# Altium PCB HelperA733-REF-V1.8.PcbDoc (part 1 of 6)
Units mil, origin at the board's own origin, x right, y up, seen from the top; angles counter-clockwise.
Board outline 5905.51 x 4133.86 mil, 2 copper layers (Top, Bottom), stack 12.7 mil thick; 475 components, 355 nets, 1867 pads, 1471 vias.
Unrouted connection lines stored in the file: 1178.
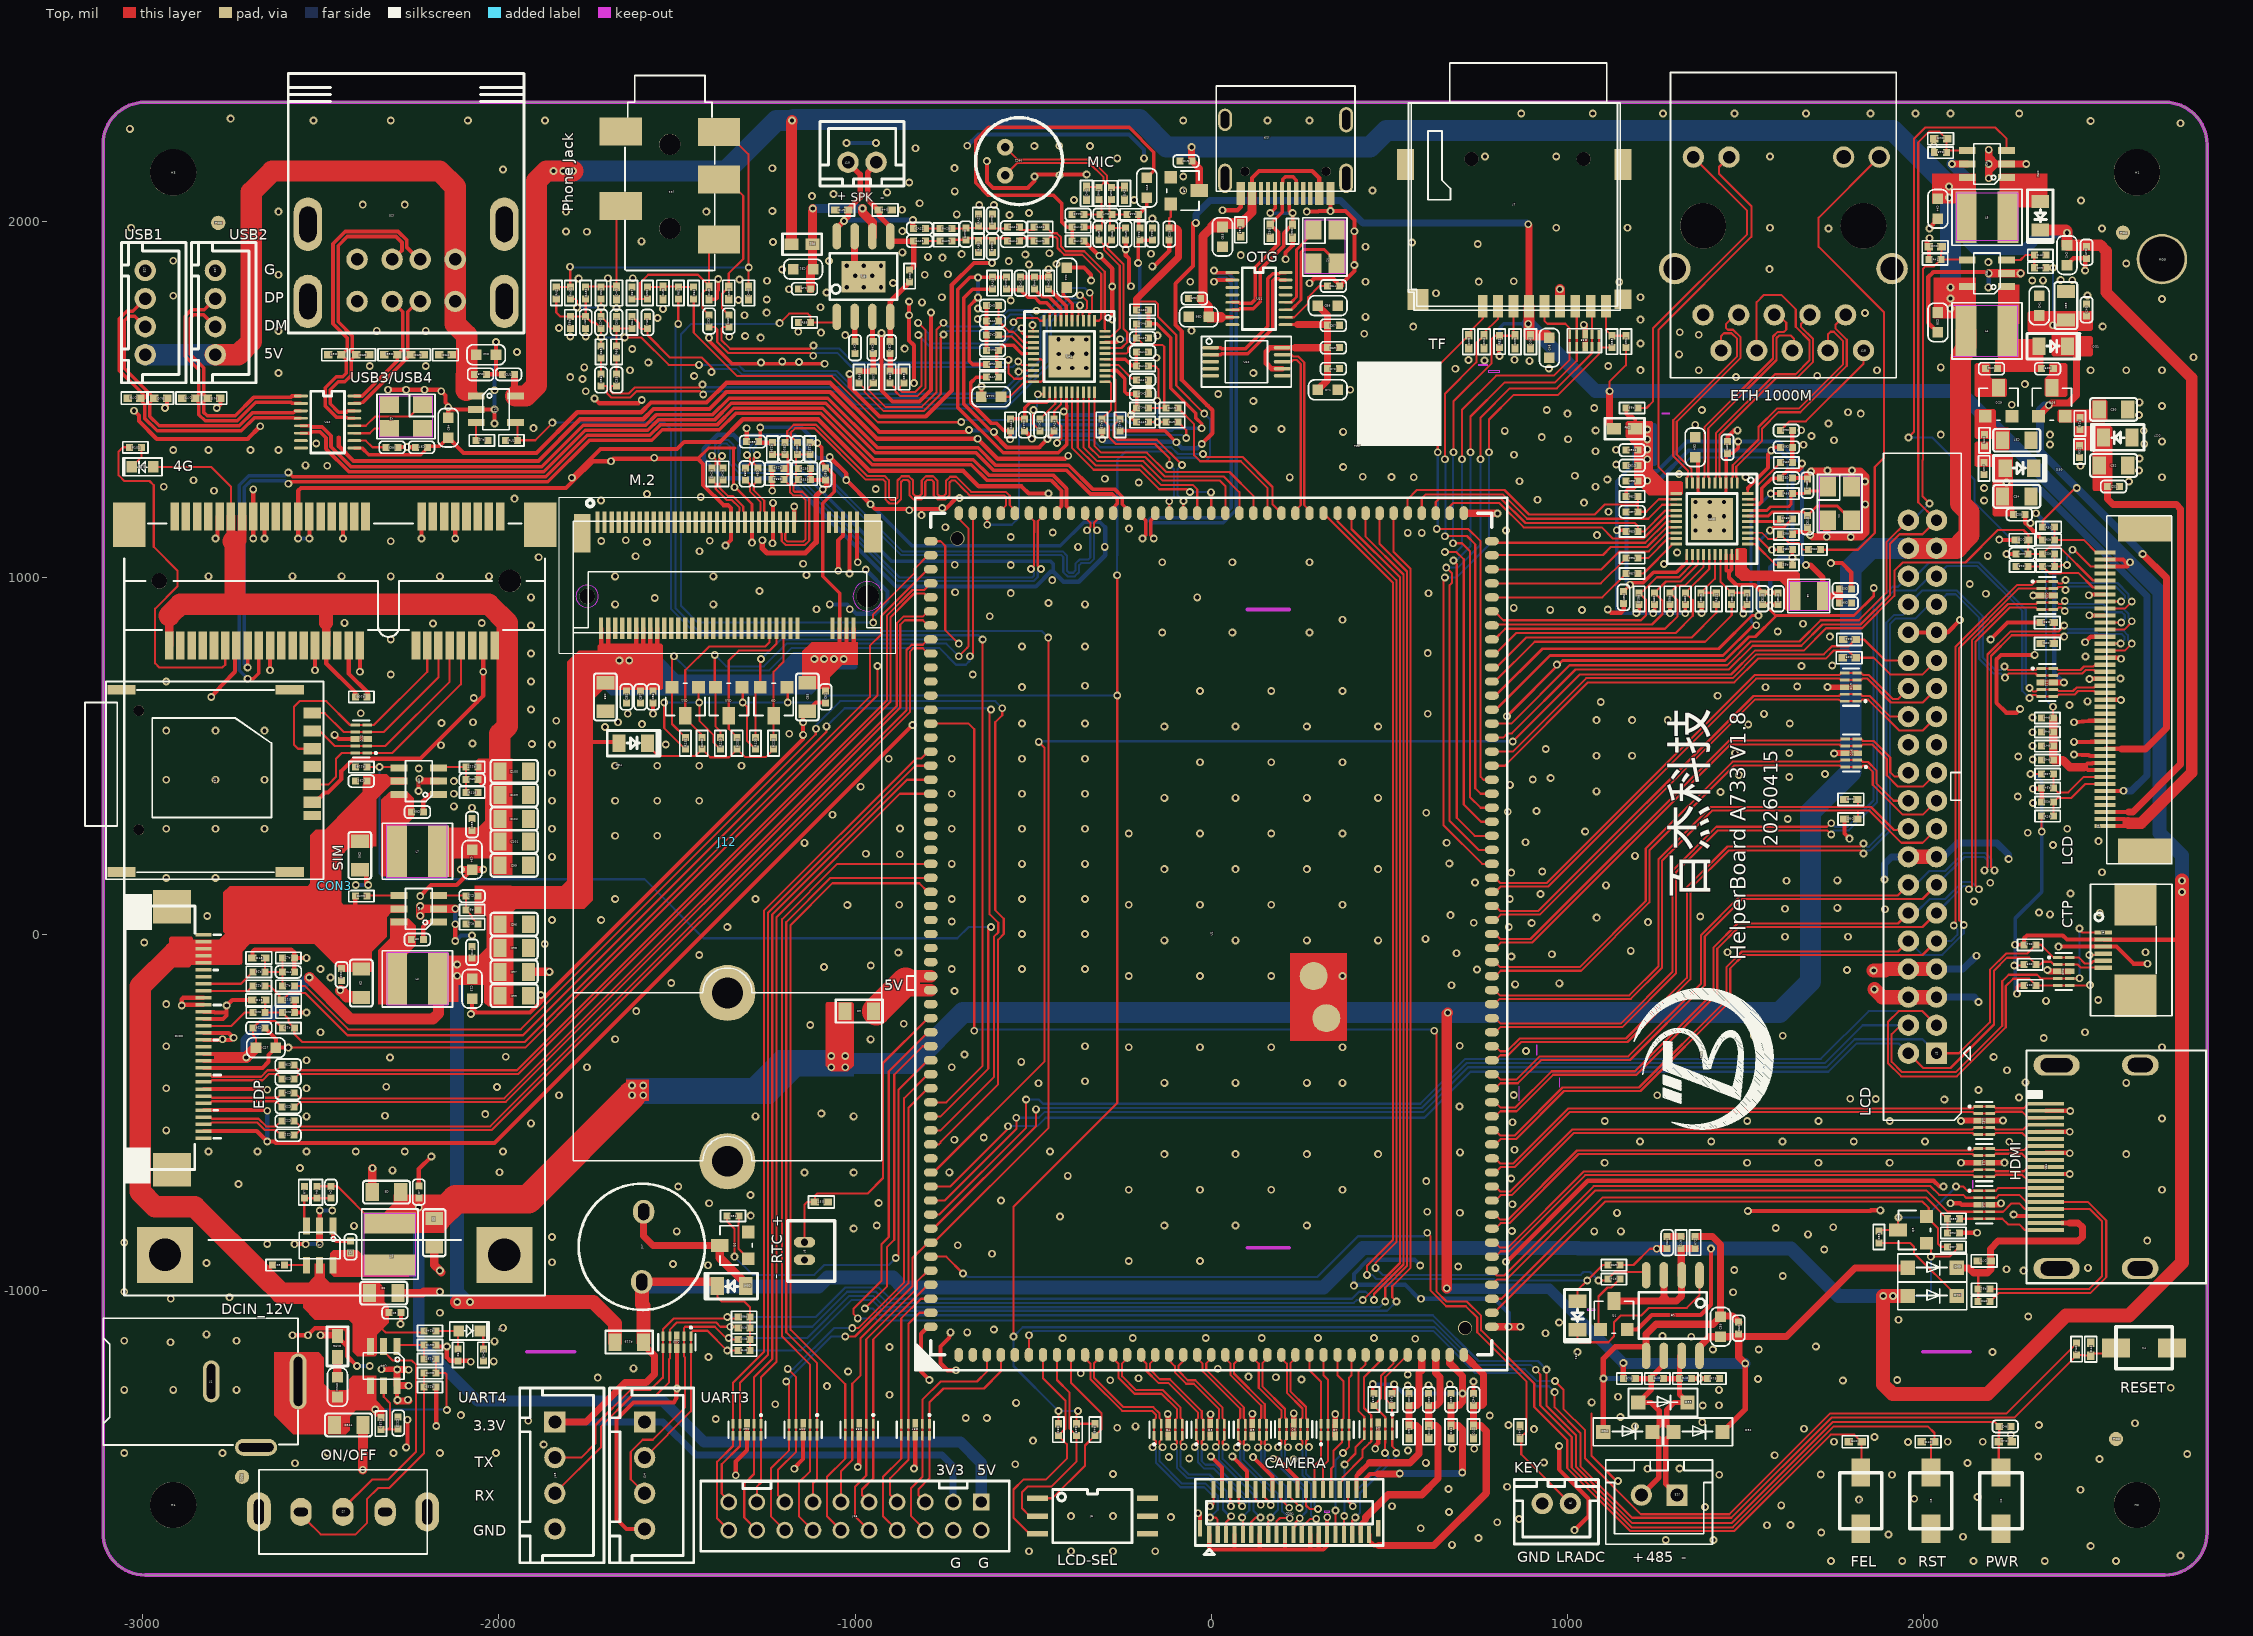
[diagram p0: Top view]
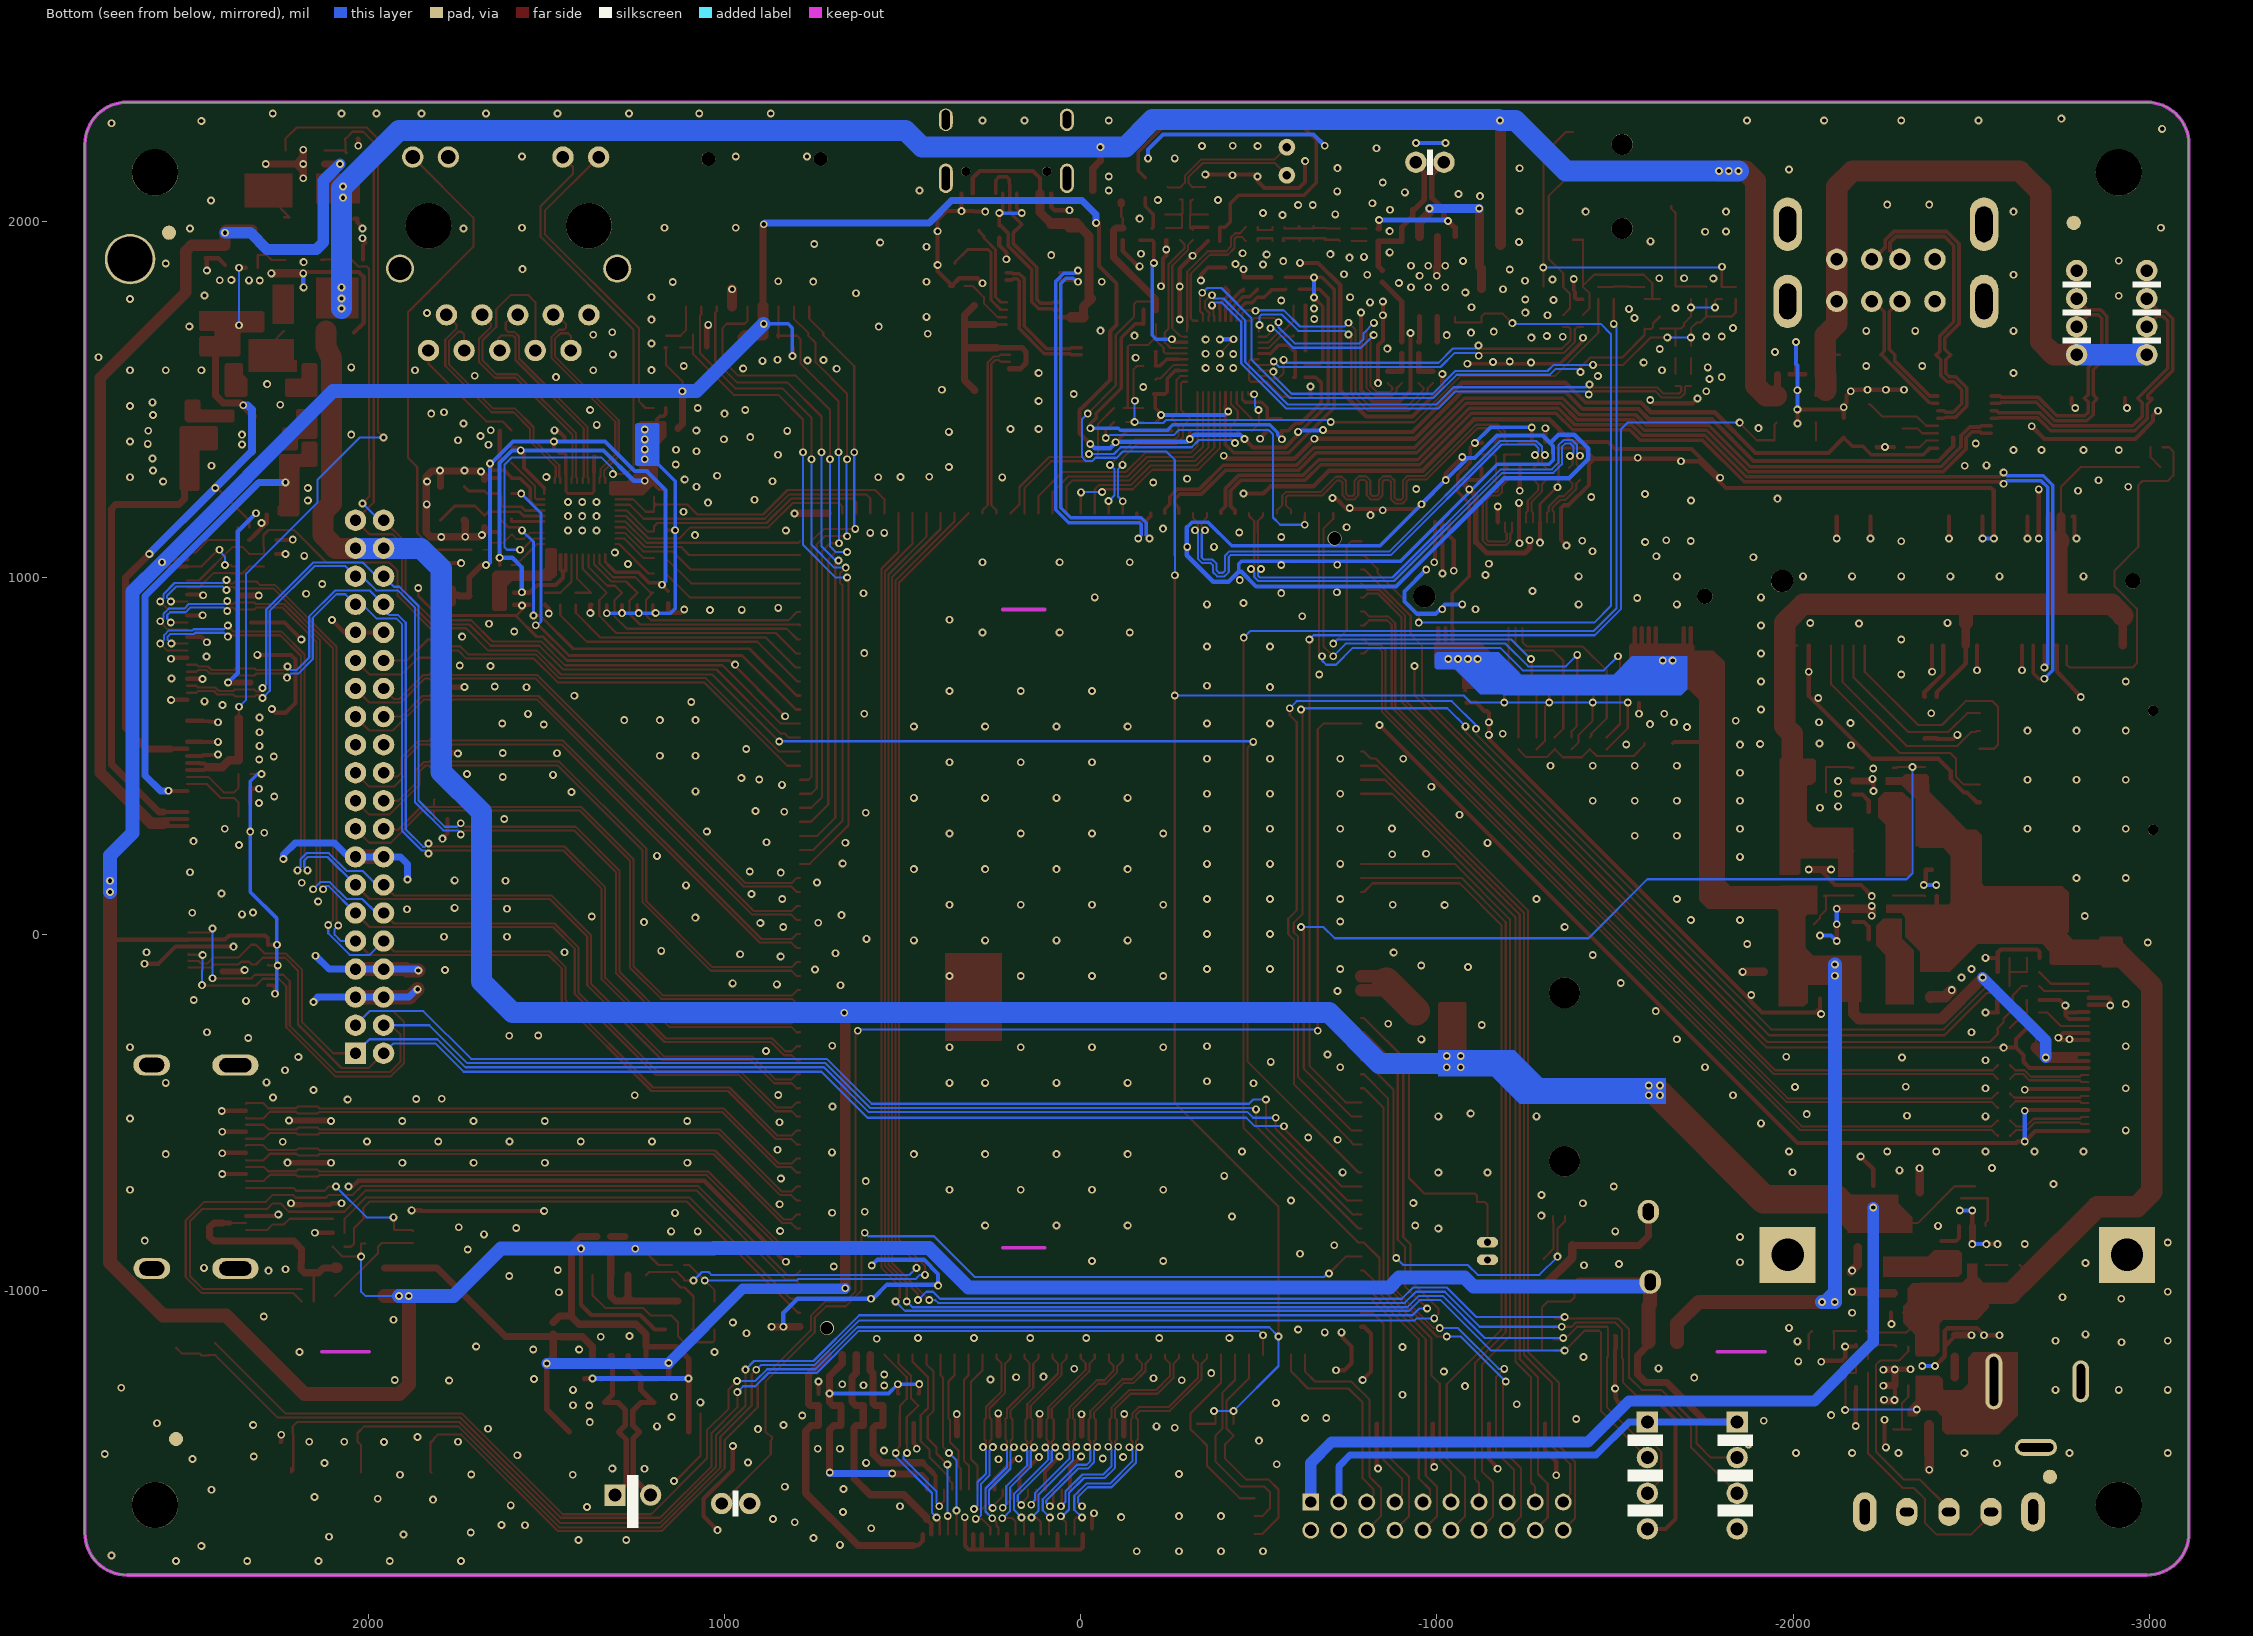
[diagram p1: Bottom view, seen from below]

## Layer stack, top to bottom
Solder Mask Top: solder mask 0.4, Solder Resist, Dk 3.5
Top: signal copper 1.35
Dielectric 1: dielectric 10, FR-4, Dk 4.3
Bottom: signal copper 1.35
Solder Mask Bottom: solder mask 0.4, Solder Resist, Dk 3.5

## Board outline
-3110.65,2216.54 cw(c-2992.54,2216.54) -2992.54,2334.65 2676.76,2334.65 cw(c2676.76,2216.54) 2794.87,2216.54 2794.87,-1681.1 cw(c2676.76,-1681.1) 2676.76,-1799.21 -2992.54,-1799.21 cw(c-2992.54,-1681.1) -3110.65,-1681.1

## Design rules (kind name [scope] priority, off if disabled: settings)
Clearance "Clearance - Net - DCIN" [InNet('DCIN')] p1: gap=6 ignorepadtopadclearanceinfootprint=FALSE except(0: Arc-Hole Track-Hole SMDPad-Hole THPad-Hole Via-Hole Fill-Hole Poly-Hole Region-Hole Text-Hole; 4: Arc-Arc Arc-Track Track-Track; 7.87: Arc-Fill Arc-Poly Arc-Region Track-Fill Track-Poly Track-Region SMDPad-Fill SMDPad-Poly SMDPad-Region THPad-Fill THPad-Poly THPad-Region Via-Fill Via-Poly Via-Region; 10: Fill-Fill Fill-Poly Fill-Region Poly-Poly Poly-Region Region-Region Text-Text)
Clearance "Clearance - Net - 340_3V3" [InNet('340_3V3') OR InNet('LED1_AD1')] p2: gap=6 ignorepadtopadclearanceinfootprint=FALSE except(0: Arc-Hole Track-Hole SMDPad-Hole THPad-Hole Via-Hole Fill-Hole Poly-Hole Region-Hole Text-Hole; 10: Fill-Fill Fill-Poly Fill-Region Poly-Poly Poly-Region Region-Region Text-Text; 12: Arc-Fill Arc-Poly Arc-Region Track-Fill Track-Poly Track-Region SMDPad-Fill SMDPad-Poly SMDPad-Region THPad-Fill THPad-Poly THPad-Region Via-Fill Via-Poly Via-Region)
Clearance "Clearance - Net - GND" [InNet('GND')] p3: gap=6 ignorepadtopadclearanceinfootprint=FALSE except(0: Arc-Hole Track-Hole SMDPad-Hole THPad-Hole Via-Hole Fill-Hole Poly-Hole Region-Hole Text-Hole; 8: Arc-Fill Arc-Poly Arc-Region Track-Fill Track-Poly Track-Region SMDPad-Fill SMDPad-Poly SMDPad-Region THPad-Fill THPad-Poly THPad-Region Via-Fill Via-Poly Via-Region; 10: Fill-Fill Fill-Poly Fill-Region Poly-Poly Poly-Region Region-Region Text-Text)
Clearance "Clearance - Net - 12V-IN" [InNet('12V-IN')] p4: gap=11.81 ignorepadtopadclearanceinfootprint=FALSE except(0: Arc-Hole Track-Hole SMDPad-Hole THPad-Hole Via-Hole Fill-Hole Poly-Hole Region-Hole Text-Hole; 10: Fill-Fill Fill-Poly Fill-Region Poly-Poly Poly-Region Region-Region Text-Text)
Clearance "Clearance - Default - DEFAULT- SMD" [IsVia vs IsSMTPin] p5: gap=0 ignorepadtopadclearanceinfootprint=FALSE
Clearance "Clearance - Default - DEFAULT - Via" [IsVia vs IsVia] p6: gap=0 ignorepadtopadclearanceinfootprint=FALSE
Clearance "Clearance - Default - DEFAULT - Net" [All] p7: gap=6 ignorepadtopadclearanceinfootprint=FALSE except(0: Arc-Hole Track-Hole SMDPad-Hole THPad-Hole Via-Hole Fill-Hole Poly-Hole Region-Hole Text-Hole; 4: Arc-Arc Arc-Track Track-Track; 10: Fill-Fill Fill-Poly Fill-Region Poly-Poly Poly-Region Region-Region Text-Text)
ComponentClearance "ComponentClearance - Default - DEFAULT" [All] p1: gap=6 collisioncheckmode=3 verticalgap=10 showdistances=FALSE
FanoutControl Fanout_SOIC [IsSOIC] p1: bgadir=Out bgaviamode=Centered fanoutstyle=Auto fanoutdirection=Alternating viagrid=1 // Fanout_SOIC (Default Rule)
FanoutControl Fanout_Small [(CompPinCount < 5)] p2: bgadir=Out bgaviamode=Centered fanoutstyle=Auto fanoutdirection=OutThenIn viagrid=1 // Fanout_Small (Default Rule)
FanoutControl Fanout_LCC [IsLCC] p3: bgadir=Out bgaviamode=Centered fanoutstyle=Auto fanoutdirection=Alternating viagrid=1 // Fanout_LCC (Default Rule)
FanoutControl Fanout_BGA [IsBGA] p4: bgadir=Out bgaviamode=Centered fanoutstyle=Auto fanoutdirection=Alternating viagrid=1 // Fanout_BGA (Default Rule)
HoleToHoleClearance "HoleToHoleClearance - Default - DEFAULT" [All] p1: gap=6 allowstackedmicrovias=TRUE
Length "Length - NetClass - HighSpeedClass_10(RuleSet)" [InNetClass('HighSpeedClass_10(RuleSet)')] p1: maxlimit=50000 minlimit=0
Length "Length - NetClass - MLNetGroup4" [InNetClass('MLNetGroup4')] p2: maxlimit=18503.27 minlimit=0
Length "Default Length" [All] p3: maxlimit=50000 minlimit=0
MatchedLengths "MatchedLengths - NetClass - HighSpeedClass_10(RuleSet)" [InNetClass('HighSpeedClass_10(RuleSet)')] p1: tolerance=200 checknetsindiffpair=FALSE checkdiffpairvsdiffpair=TRUE checkxsignals=TRUE checkothers=TRUE
MatchedLengths "MatchedLengths - NetClass - MLNetGroup4" [InNetClass('MLNetGroup4')] p2: tolerance=200 checknetsindiffpair=FALSE checkdiffpairvsdiffpair=TRUE checkxsignals=TRUE checkothers=TRUE
MaxMinImpedance "Default Impedance" [All] p1: minimum=50.00 maximum=150.0
ParallelSegment "ParallelSegment - NetClass - HighSpeedClass_10(RuleSet)_1" [InNetClass('HighSpeedClass_10(RuleSet)') vs InNetClass('HighSpeedClass_10(RuleSet)')] p1: limit=1000 gap=200
ParallelSegment "ParallelSegment - NetClass - HighSpeedClass_10(RuleSet)" [InNetClass('HighSpeedClass_10(RuleSet)') vs InNetClass('HighSpeedClass_10(RuleSet)')] p2: limit=1000 gap=200
ParallelSegment "Default Parallel Segment Adjasent" [All] p3: limit=1000 gap=200
ParallelSegment "Default Parallel Segment Same Layer" [All] p4: limit=1000 gap=200
PlaneConnect "Default PlaneConnect" [All] p1: planeconnectstyle=Relief reliefexpansion=20 reliefentries=0 reliefconductorwidth=15 reliefairgap=10
PolygonConnect "PolygonConnect - Default SMT" [IsSMTPin] p1: connectstyle=Relief reliefconductorwidth=10 reliefentries=4 polygonreliefangle="90 Angle" airgapwidth=10
PolygonConnect "PolygonConnect - Default Pad" [All] p2: connectstyle=Relief reliefconductorwidth=15 reliefentries=4 polygonreliefangle="45 Angle" airgapwidth=10
RoutingLayers "RoutingLayers - Default - DEFAULT" [All] p1: top layer_v5=TRUE bottom layer_v5=TRUE
RoutingPriority "RoutingPriority - Default - DEFAULT" [All] p1: routingpriority=3
RoutingTopology "Default Routing Topology" [All] p1: topology=Shortest
RoutingVias "RoutingVias - Default - DEFAULT" [All] p1: holewidth=12 width=22 viastyle="Through Hole" minholewidth=12 minwidth=22 maxholewidth=12 maxwidth=22
SMDToCorner "SMDToCorner - Default - DEFAULT" [All] p1: distance=0
SolderMaskExpansion [All] p1: expansion=4
Width "Width - Net - LED1_AD1" [InNet('LED1_AD1')] p1: maxlimit=200 minlimit=5 preferedwidth=5
Width "Width - Net - GND" [InNet('GND')] p2: maxlimit=200 minlimit=5 preferedwidth=11.81
Width "Width - Net - 340_3V3" [InNet('340_3V3')] p3: maxlimit=200 minlimit=5 preferedwidth=15
Width "Default Width" [All] p4: maxlimit=200 minlimit=6 preferedwidth=6
18 further rules are at their usual default settings.

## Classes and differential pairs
net class MLNetGroup1: N18103307 N18103321 PCIE1-REFCLKN PCIE1-REFCLKP PCIE1-RXN PCIE1-RXP PCIE1-TXN PCIE1-TXP REFCLKN REFCLKP
net class MLNetGroup4: LVDS0-D0N LVDS0-D0P LVDS0-D1N LVDS0-D1P LVDS0-D2N LVDS0-D2P
net class HighSpeedClass_10(RuleSet): PCIE1-REFCLKN PCIE1-REFCLKP PCIE1-RXN PCIE1-RXP PCIE1-TXN PCIE1-TXP
net class RoutingClass_12(RuleSet): 340_3V3 GND LED1_AD1

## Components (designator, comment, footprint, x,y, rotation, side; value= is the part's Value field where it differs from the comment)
C1 "C0402" C0402 -2415.94,-878.33 r270 top
C2 "C0805" C0805 -2322.83,-1007.87 r0 top
C3 "C0402" C0402 -2291.34,-1062.99 r0 top
C4 "C0402" C0402 -2471.06,-724.79 r270 top
C5 "C0805" C0805 -2181.1,-838.58 r270 top
C6 "C0805" C0805 -2314.96,-724.41 r180 top
C7 "C0402" C0402 -2224.41,-724.41 r90 top
C8 "C0402" C0402 -2228.35,-15.75 r180 top
C9 "C0805" C0805 -2385.83,-137.8 r270 top
C10 "C0402" C0402 -2440.94,-114.17 r270 top
C11 "C0402" C0402 -2074.8,106.3 r180 top
C12 "C0402" C0402 -2074.8,-51.18 r90 top
C13 "C0603" C0603 -2074.8,-153.54 r270 top
C19 "C0402" C0402 -70.87,2169.29 r0 top
C20 "C0402" C0402 -118.11,1964.57 r90 top
C21 "C0402" C0402 -2591.24,-564.71 r180 top
C22 "C0402" C0402 -2591.24,-525.34 r180 top
C23 "C0402" C0402 -2591.24,-485.97 r180 top
C24 "C0402" C0402 -2591.24,-446.6 r180 top
C25 "C0402" C0402 -2591.24,-407.23 r180 top
C26 "C0402" C0402 -2673.23,-263.78 r180 top
C27 "C0603" C0603 -2653.54,-318.9 r0 top
C28 "C0402" C0402 -2591.24,-367.86 r180 top
C29 "C0402" C0402 2347.44,1586.61 r180 top
C30 "C0805" C0805 2532.48,1472.44 r0 top
C31 "C0402" C0402 2532.48,1255.91 r0 top
C32 "C0805" C0805 2532.48,1314.96 r0 top
C33 "C0402" C0402 2275.59,1066.93 r0 top
C34 "C0805" C0805 2260.83,1228.35 r0 top
C35 "C0402" C0402 2267.72,1177.17 r0 top
C36 "C0402" C0402 2189.96,1586.61 r180 top
C37 "C0805" C0805 2260.83,1385.83 r180 top
C38 "C0603" C0603 2039.37,1716.54 r270 top
C39 "C0805" C0805 2398.62,1763.78 r90 top
C40 "C0402" C0402 2456.69,1751.97 r90 top
C41 "C0603" C0603 2323.82,1763.78 r90 top
C42 "C0603" C0603 2401.57,1905.51 r270 top
C43 "C0402" C0402 2456.69,1913.39 r270 top
C44 "C0603" C0603 2039.37,2035.43 r270 top
C45 "C0603" C0603 948.82,1645.67 r90 top
C46 "C0402" C0402 2228.35,-1381.89 r0 top
C47 "C0402" C0402 -1000,1645.67 r270 top
C48 "C0402" C0402 -948.82,1645.67 r270 top
C49 "C0402" C0402 -1141.73,1811.02 r180 top
C50 "C0402" C0402 -901.57,1645.67 r270 top
C51 "C0603" C0603 -1145.67,1866.14 r180 top
C52 "C0402" C0402 -1409.45,1720.47 r270 top
C53 "C0402" C0402 -1354.33,1720.47 r270 top
C54 "C0402" C0402 -1582.68,1716.54 r270 top
C55 "C0402" C0402 -1669.29,1555.12 r90 top
C56 "C0402" C0402 -1712.6,1555.12 r90 top
C57 "C0402" C0402 -1755.91,1716.54 r270 top
C58 "C0402" C0402 -1669.29,1716.54 r90 top
C59 "C0603" C0603 1429.13,-1102.36 r90 top
C60 "C0402" C0402 1480.32,-1106.3 r90 top
C61 "C0402" C0402 1279.53,-866.14 r90 top
C62 "C0402" C0402 1614.17,1413.39 r180 top
C63 "C0603" C0603 31.5,1956.69 r90 top
C64 "C0402" C0402 342.52,1818.9 r0 top
C65 "C0402" C0402 -47.24,1783.46 r180 top
C66 "C0603" C0603 -35.43,1732.28 r180 top
C67 "C0402" C0402 342.52,1708.66 r0 top
C68 "C0603" C0603 326.77,1763.78 r0 top
C69 "C0402" C0402 342.52,1645.67 r0 top
C70 "C0402" C0402 342.52,1586.61 r0 top
C71 "C0603" C0603 326.77,1527.56 r0 top
C84 "C0603" C0603 -2141.73,1421.26 r90 top
C86 "C0402" C0402 -2299.21,1366.14 r0 top
C87 "C0402" C0402 -2216.54,1366.14 r180 top
C88 "C0805" C0805 -1700.79,665.35 r270 top
C89 "C0402" C0402 -2228.35,342.52 r180 top
C90 "C0805" C0805 -2389.76,220.47 r270 top
C91 "C0402" C0402 -2385.83,429.13 r180 top
C92 "C0402" C0402 -2074.8,433.07 r180 top
C93 "C0402" C0402 -2074.8,307.09 r90 top
C94 "C0603" C0603 -2074.8,208.66 r270 top
C95 "C0805" C0805 -1956.69,-173.23 r0 top
C96 "C0805" C0805 -1956.69,27.56 r0 top
C97 "C0805" C0805 -1956.69,-106.3 r0 top
C98 "C0805" C0805 -1956.69,-39.37 r0 top
C99 "C0805" C0805 -1956.69,192.91 r0 top
C100 "C0805" C0805 -1956.69,456.69 r0 top
C101 "C0805" C0805 -1956.69,259.84 r0 top
C102 "C0805" C0805 -1956.69,322.83 r0 top
C103 "C0805" C0805 -1956.69,389.76 r0 top
C322 "C0603" C0603 -2452.76,-1271.65 r270 top
C323 "C0402" C0402 -2282.08,-1372.69 r270 top
C324 "C0805" C0805 -2421.26,-1377.95 r0 top
CA1 "C0603" C0603 -405.51,1842.52 r270 top
CA2 "C0402" C0402 -614.17,1681.1 r180 top
CA3 "C0402" C0402 -614.17,1763.78 r0 top
CA4 "C0402" C0402 -165.35,1964.57 r270 top
CA5 "C0402" C0402 -240.16,1964.57 r90 top
CA6 "C0402" C0402 -279.53,1964.57 r90 top
CA7 "C0402" C0402 -295.28,2019.68 r180 top
CA8 "C0603" C0603 -181.1,2094.49 r90 top
CA9 "C0402" C0402 -314.96,1964.57 r90 top
CA10 "C0402" C0402 -614.17,1637.8 r180 top
CA11 "C0402" C0402 -192.91,1633.86 r0 top
CA12 "C0402" C0402 -374.02,2019.68 r180 top
CA13 "C0402" C0402 -523.62,1429.13 r270 top
CA14 "C0402" C0402 -535.43,1826.77 r90 top
CA15 "C0402" C0402 -192.91,1673.23 r0 top
CA16 "C0402" C0402 -192.91,1515.75 r180 top
CA17 "C0402" C0402 -192.91,1555.12 r0 top
CA18 "C0603" C0603 -618.11,1507.87 r180 top
CA19 "C0402" C0402 -480.31,1429.13 r270 top
CA20 "C0402" C0402 -614.17,2003.94 r270 top
CA21 "C0402" C0402 -555.12,1984.25 r0 top
CA22 "C0402" C0402 -818.9,1980.31 r0 top
CA23 "C0402" C0402 -688.98,1964.57 r270 top
CA24 "C0402" C0402 -555.12,1944.88 r0 top
CA25 "C0402" C0402 -818.9,1944.88 r0 top
CA26 "C0402" C0402 -614.17,1929.13 r270 top
CA27 "C0402" C0402 -1712.6,1716.54 r270 top
CB1 "C0402" C0402 -1082.68,665.35 r90 top
CB2 "C0402" C0402 -1641.73,665.35 r90 top
CB3 "C0805" C0805 -1133.86,665.35 r90 top
CB4 "C0402" C0402 -1271.65,1291.34 r270 top
CB5 "C0402" C0402 -1307.09,1291.34 r270 top
CB6 "C0402" C0402 -1566.93,665.35 r90 top
CB7 "C0402" C0402 -1602.36,665.35 r90 top
CB8 "C0402" C0402 -1082.68,1291.34 r90 top
CB9 "C0402" C0402 -1287.4,1381.89 r0 top
CB10 "C0402" C0402 -1196.85,1362.2 r270 top
CB11 "C0402" C0402 -1161.42,1362.2 r270 top
CE1 "C0402" C0402 1614.17,1279.53 r180 top
CE2 "C0402" C0402 1157.48,944.88 r90 top
CE3 "C0402" C0402 1779.53,968.5 r180 top
CE4 "C0603" C0603 1358.27,1366.14 r270 top
CE5 "C0402" C0402 1448.82,1366.14 r270 top
CE6 "C0402" C0402 1779.53,929.13 r180 top
CE7 "C0402" C0402 1181.1,1185.04 r0 top
CE8 "C0402" C0402 1181.1,1271.65 r0 top
CE9 "C0402" C0402 1614.17,1366.14 r180 top
CE10 "C0402" C0402 1547.24,940.94 r90 top
CE11 "C0402" C0402 1181.1,1358.27 r0 top
CE12 "C0402" C0402 1590.55,940.94 r90 top
CE13 "C0402" C0402 1181.1,1314.96 r0 top
CE14 "C0402" C0402 1673.23,1259.84 r270 top
CE15 "C0402" C0402 1673.23,1157.48 r90 top
CL1 "C0402" C0402 -2590.55,-106.3 r0 top
CON1 "FH35C-39S-0.3SHW" FH35C-39S-0.3SHW 218.63,-1625.95 r0 top
CON2 "FPC30-0.5-1" FPC30-0.5-1 -2897.64,-287.4 r180 top
CON3 "MINI_PCIEX1-52P-5.2H" MINI_PCIEX1-52P-5.2H -2460.63,-39.37 r180 top
CP1 "C0402" C0402 555.12,-1307.09 r90 top
CP2 "C0402" C0402 610.24,-1307.09 r90 top
CP3 "C0402" C0402 673.23,-1307.09 r90 top
CP4 "C0402" C0402 736.22,-1307.09 r90 top
CU1 "C0402" C0402 -1972.44,1570.87 r0 top
CU2 "C0603" C0603 -2035.43,1625.98 r180 top
CU3 "C0402" C0402 -2051.18,1570.87 r180 top
D2 "D0603" D0603 -2082.68,-1114.17 r0 top
D3 "DFN2510-10_L2.5-W1.0-P0.50-BL" DFN2510-10_L2.5-W1.0-P0.50-BL -2.93,-1391.3 r0 top
D4 "DFN2510-10_L2.5-W1.0-P0.50-BL" DFN2510-10_L2.5-W1.0-P0.50-BL -121.04,-1391.3 r0 top
D5 "DFN2510-10_L2.5-W1.0-P0.50-BL" DFN2510-10_L2.5-W1.0-P0.50-BL 115.18,-1391.3 r0 top
D6 "DFN2510-10_L2.5-W1.0-P0.50-BL" DFN2510-10_L2.5-W1.0-P0.50-BL 231,-1390.41 r0 top
D7 "DFN2510-10_L2.5-W1.0-P0.50-BL" DFN2510-10_L2.5-W1.0-P0.50-BL 347.47,-1391.3 r0 top
D8 "DFN2510-10_L2.5-W1.0-P0.50-BL" DFN2510-10_L2.5-W1.0-P0.50-BL 468.5,-1389.76 r180 top
D9 "ESD0402" ESD0402 555.12,-1397.64 r90 top
D10 "ESD0402" ESD0402 610.24,-1397.64 r90 top
D11 "ESD0402" ESD0402 673.23,-1397.64 r90 top
D12 "ESD0402" ESD0402 736.22,-1397.64 r90 top
D13 "DFN2510-10_L2.5-W1.0-P0.50-BL" DFN2510-10_L2.5-W1.0-P0.50-BL 2346.46,950.11 r270 top
D15 "ESD0402" ESD0402 -2673.23,-185.04 r0 top
D16 "DFN2510-10_L2.5-W1.0-P0.50-BL" DFN2510-10_L2.5-W1.0-P0.50-BL 1796.26,507.87 r90 top
D17 "ESD0402" ESD0402 -2590.55,-185.04 r180 top
D18 "ESD0402" ESD0402 -2673.23,-66.93 r0 top
D19 "DFN2510-10_L2.5-W1.0-P0.50-BL" DFN2510-10_L2.5-W1.0-P0.50-BL 1795.28,692.91 r90 top
D20 "DFN2510-10_L2.5-W1.0-P0.50-BL" DFN2510-10_L2.5-W1.0-P0.50-BL 2392.49,-105.06 r270 top
D21 "DFN2510-10_L2.5-W1.0-P0.50-BL" DFN2510-10_L2.5-W1.0-P0.50-BL 2346.46,706.02 r270 top
D22 "ESD0402" ESD0402 2031.5,1929.13 r180 top
D23 "ESD0402" ESD0402 2047.24,2232.28 r180 top
D24 "ESD0402" ESD0402 1791.34,826.77 r180 top
D25 "ESD0402" ESD0402 1790.43,775.5 r180 top
D26 "SOT23" SOT23 2359.25,1492.13 r0 top
D27 "D0805" D0805 2544.29,1393.7 r180 top
D28 "ESD0402" ESD0402 2275.59,1106.3 r180 top
D29 "SOT23" SOT23 2209.65,1492.13 r0 top
D30 "D0805" D0805 2268.7,1307.09 r0 top
D31 "D0805" D0805 2363.19,1649.61 r0 top
D32 "SOD323" SOD323 2326.77,2015.75 r270 top
D33 "ESD0402" ESD0402 722.56,1662.47 r90 top
D34 "ESD0402" ESD0402 765.86,1662.47 r90 top
D35 "ESD0402" ESD0402 852.48,1662.47 r90 top
D36 "ESD0402" ESD0402 895.79,1662.47 r90 top
D37 "ESD0402" ESD0402 -1094.49,-751.97 r180 top
D38 "RCLAMP0524P" RCLAMP0524P 1047.24,1665.35 r180 top
D39 "ESD0402" ESD0402 1807.09,-1425.2 r180 top
D40 "ESD0402" ESD0402 2011.81,-1425.2 r0 top
D41 "ESD0402" ESD0402 2228.35,-1425.2 r180 top
D42 "ESD0402" ESD0402 2468.5,-1165.35 r90 top
D43 "ESD0402" ESD0402 866.14,-1397.64 r270 top
D44 "ESD0402" ESD0402 -915.4,2032.62 r180 top
D45 "ESD0402" ESD0402 -1037.45,2032.62 r0 top
D46 "ESD0402" ESD0402 -1299.21,1799.21 r90 top
D47 "ESD0402" ESD0402 -1669.29,1799.21 r90 top
D48 "ESD0402" ESD0402 -1409.45,1799.21 r90 top
D49 "ESD0402" ESD0402 -1539.37,1799.21 r90 top
D50 "ESD0402" ESD0402 -1354.33,1799.21 r90 top
D51 "SOD323" SOD323 1027.56,-1070.87 r270 top
D52 "SOD123" SOD123 1366.14,-1397.64 r0 top
D53 "SOD123" SOD123 1267.72,-1314.96 r0 top
D54 "SOD123" SOD123 1169.29,-1397.64 r0 top
D55 "DFN2510-10_L2.5-W1.0-P0.50-BL" DFN2510-10_L2.5-W1.0-P0.50-BL -1500,-1145.67 r180 top
D56 "SOD323" SOD323 -1346.46,-988.19 r180 top
D57 "DFN2510-10_L2.5-W1.0-P0.50-BL" DFN2510-10_L2.5-W1.0-P0.50-BL -830.71,-1391.34 r180 top
D58 "DFN2510-10_L2.5-W1.0-P0.50-BL" DFN2510-10_L2.5-W1.0-P0.50-BL -988.19,-1391.34 r180 top
D59 "DFN2510-10_L2.5-W1.0-P0.50-BL" DFN2510-10_L2.5-W1.0-P0.50-BL -1145.67,-1391.34 r180 top
D60 "DFN2510-10_L2.5-W1.0-P0.50-BL" DFN2510-10_L2.5-W1.0-P0.50-BL -1303.15,-1391.34 r180 top
D61 "ESD0402" ESD0402 228.35,1972.44 r270 top
D62 "ESD0402" ESD0402 165.35,1972.44 r270 top
D63 "ESD0402" ESD0402 82.68,1976.38 r270 top
D64 "ESD0402" ESD0402 -2149.61,1625.98 r0 top
D65 "ESD0402" ESD0402 -2228.35,1625.98 r0 top
D66 "ESD0402" ESD0402 -2303.15,1625.98 r180 top
D67 "ESD0402" ESD0402 -2460.63,1625.98 r180 top
D68 "ESD0402" ESD0402 -2381.89,1625.98 r0 top
D69 "SOD123" SOD123 2023.62,-937.01 r0 top
D70 "SOD123" SOD123 2023.62,-1015.75 r0 top
D71 "ESD0402" ESD0402 2169.29,-917.32 r180 top
D72 "DFN2510-10_L2.5-W1.0-P0.50-BL" DFN2510-10_L2.5-W1.0-P0.50-BL -2385.83,547.24 r90 top
D73 "D0603" D0603 -3000,1311.02 r180 top
D76 "ESD0402" ESD0402 -2799.21,1503.94 r0 top
D77 "ESD0402" ESD0402 -2870.08,1503.94 r180 top
D78 "ESD0402" ESD0402 -2948.82,1503.94 r0 top
D79 "ESD0402" ESD0402 -3023.62,1503.94 r180 top
D80 "ESD0402" ESD0402 2346.46,874.02 r180 top
D81 "ESD0402" ESD0402 2346.46,814.96 r180 top
D82 "ESD0402" ESD0402 1795.28,322.83 r180 top
D83 "ESD0402" ESD0402 1795.28,377.95 r180 top
D84 "SOD323" SOD323 -1622.05,535.43 r0 top
DA1 "ESD0402" ESD0402 -350.39,2078.74 r90 top
DA2 "ESD0402" ESD0402 -244.09,2078.74 r90 top
DE1 "DFN2510-10_L2.5-W1.0-P0.50-BL" DFN2510-10_L2.5-W1.0-P0.50-BL 2169.29,-523.62 r270 top
FB1 "L0603" L0603 -1118.11,1937.01 r180 top
FB2 "L0603" L0603 1129.92,1417.32 r0 top
FID1 "MARK" MARK -2720.47,-1523.62 r270 top
FID2 "MARK" MARK 2539.37,-1417.32 r0 top
FID3 "MARK" MARK -2787.4,1996.06 r0 top
FID4 "MARK" MARK 2559.06,1968.5 r0 top
FID5 "DVE" DVE 2668.22,1894.12 r0 top
H1 "DVA" DVA 2598.02,2137.8 r0 top
H2 "DVA" DVA 2598.02,-1602.36 r0 top
H3 "DVA" DVA -2913.8,2137.8 r0 top
H4 "DVA" DVA -2913.8,-1602.36 r0 top
J1 "DC470" DC470 -2807.09,-1255.91 r0 top
J2 "SS-12F44(1P2T)" SS-12F44(1P2T) -2437.01,-1622.05 r180 top
J3 "HDR2X20$2F$2.0" HDR2X20$2F$2.0 2035.43,-334.65 r90 top
J4 "FPC40-0.5MM-UP" FPC40-0.5MM-UP 2488.19,303.15 r90 top
J5 "FPC_0.5_6P_DOWN" FPC_0.5_6P_DOWN 2503.94,3.94 r270 top
J6 "SW-1.27-6P" SW-1.27-6P -334.65,-1633.86 r0 top
J7 "TF_PUSH1" TF_PUSH1 850.39,2047.24 r0 top
J8 "MX1.25-2P" MX1.25-2P -1141.73,-889.76 r90 top
J9 "PH-2.0-2P" PH-2.0-2P 1007.87,-1598.43 r180 top
J10 "PH-2.0-2P" PH-2.0-2P -1019.66,2166.23 r0 top
J11 "PJ327F" PJ327F -1637.8,2334.65 r270 top
J12 "M.2-M-KEY" M.2-M-KEY -1358.27,1007.87 r0 top
J13 "XH-2.54-2P" XH-2.54-2P 1307.09,-1574.8 r180 top
J14 "XH-2.54-4P" XH-2.54-4P -1590.55,-1519.69 r90 top
J15 "XH-2.54-4P" XH-2.54-4P -1842.52,-1519.69 r90 top
J16 "PHD2.0-2X10" PHD2.0-2X10 -1000,-1633.86 r0 top
J17 "BEEP_9042" BEEP_9042 -1598.43,-877.95 r90 top
J18 "HY911130A" HY911130A 1830.71,1637.8 r0 top
J19 "USB_C" USB_C 334.65,2078.74 r180 top
J20 "USB-2A-03" USB-2A-03 -2122.05,1775.59 r180 top
J21 "NANO-SIM-7P" NANO-SIM-7P -2795.28,429.13 r270 top
J22 "PH-2.0-4P" PH-2.0-4P -2795.28,1862.2 r270 top
J23 "PH-2.0-4P" PH-2.0-4P -2992.13,1862.2 r270 top
K1 "KEY_3X4" KEY_3X4 1822.83,-1590.55 r270 top
K2 "KEY_3X4" KEY_3X4 2216.54,-1590.55 r90 top
K3 "KEY_3X4" KEY_3X4 2019.69,-1590.55 r90 top
K4 "KEY_3X4" KEY_3X4 2618.11,-1161.42 r0 top
L1 "4018" 4018 -2305.71,-870.46 r90 top
L2 "4018" 4018 -2228.35,-125.98 r0 top
L4 "4018" 4018 2177.17,1692.91 r0 top
L5 "4018" 4018 2177.17,2011.81 r0 top
L6 "SML2520_1P2H$2F$4" SML2520_1P2H$2F$4 1677.17,948.82 r270 top
L7 "4018" 4018 -2228.35,232.28 r0 top
MIC1 "MIC6050" MIC6050 -539.37,2169.29 r180 top
Q1 "SOT23" SOT23 1129.92,-1070.87 r0 top
Q2 "SOT23" SOT23 -1338.58,-874.02 r90 top
Q3 "SOT23" SOT23 1968.5,-830.71 r90 top
Q9 "SOT23" SOT23 -1228.35,653.54 r180 top
Q10 "SOT23" SOT23 -1354.33,653.54 r180 top
Q11 "SOT23" SOT23 -1476.38,653.54 r180 top
R3 "R0805" R0805 -988.19,-216.54 r0 top
R4 "R0402" R0402 -2510.43,-724.79 r270 top
R5 "R0402" R0402 -2618.11,-929.13 r0 top
R6 "R0402" R0402 -2114.17,-1181.1 r90 top
R7 "R0402" R0402 -2545.87,-724.79 r90 top
R9 "R0402" R0402 -2074.8,66.93 r180 top
R11 "R0402" R0402 -2074.8,27.56 r180 top
R15 "R0402" R0402 456.06,-1306.87 r270 top
R16 "R0402" R0402 507.24,-1306.87 r270 top
R17 "R0402" R0402 2350.39,1031.5 r180 top
R18 "R0402" R0402 2275.59,1031.5 r180 top
R19 "R0402" R0402 -2590.55,-263.78 r180 top
R20 "R0402" R0402 -2590.55,-220.47 r180 top
R21 "R0402" R0402 -2673.23,-220.47 r180 top
R22 "R0402" R0402 -2673.23,-145.67 r180 top
R23 "R0402" R0402 2298.01,-144.43 r180 top
R24 "R0402" R0402 2298.01,-30.25 r180 top
R25 "R0402" R0402 2298.01,-85.37 r180 top
R26 "R0402" R0402 -2673.23,-106.3 r180 top
R27 "R0402" R0402 2347.44,448.82 r0 top
R28 "R0402" R0402 2347.44,330.71 r0 top
R29 "R0402" R0402 2437.99,1433.07 r270 top
R30 "R0402" R0402 2350.39,1141.73 r0 top
R31 "R0402" R0402 2350.39,1066.93 r180 top
R32 "R0402" R0402 2437.01,1354.33 r90 top
R33 "R0402" R0402 2170.28,1385.83 r270 top
R34 "R0402" R0402 2347.44,409.45 r180 top
R35 "R0402" R0402 2347.44,370.08 r180 top
R36 "R0402" R0402 2350.39,1106.3 r180 top
R37 "R0402" R0402 2169.29,1307.09 r90 top
R39 "R0402" R0402 2326.77,1870.08 r0 top
R41 "R0402" R0402 2031.5,1893.7 r0 top
R42 "R0402" R0402 2326.77,1905.51 r0 top
R43 "R0402" R0402 2047.24,2192.91 r180 top
R44 "R0402" R0402 2346.46,606.3 r180 top
R45 "R0402" R0402 2346.46,488.19 r180 top
R46 "R0402" R0402 2346.46,566.93 r180 top
R47 "R0402" R0402 2346.46,527.56 r180 top
R48 "R0402" R0402 -326.77,-1391.34 r270 top
R49 "R0402" R0402 -377.95,-1391.34 r270 top
R50 "R0402" R0402 -429.13,-1391.34 r270 top
R51 "R0402" R0402 1163.5,1662.47 r90 top
R52 "R0402" R0402 809.17,1662.47 r90 top
R53 "R0402" R0402 1124.13,1662.47 r90 top
R54 "R0402" R0402 2429.13,-1165.35 r270 top
R55 "R0402" R0402 -1141.73,1716.54 r0 top
R56 "R0402" R0402 -988.19,1562.99 r90 top
R57 "R0402" R0402 -948.82,1562.99 r90 top
R58 "R0402" R0402 -846.46,1846.46 r90 top
R59 "R0402" R0402 -862.2,1562.99 r90 top
R60 "R0402" R0402 -901.57,1562.99 r90 top
R61 "R0402" R0402 -1496.06,1799.21 r90 top
R62 "R0402" R0402 -1452.76,1799.21 r90 top
R63 "R0402" R0402 -1582.68,1799.21 r270 top
R64 "R0402" R0402 -1625.98,1716.54 r90 top
R65 "R0402" R0402 -1799.21,1716.54 r270 top
R66 "R0402" R0402 -1669.29,1633.86 r90 top
R67 "R0402" R0402 -1625.98,1799.21 r90 top
R68 "R0402" R0402 -1712.6,1633.86 r90 top
R69 "R0402" R0402 1129.92,-929.13 r0 top
R70 "R0402" R0402 1173.23,-1248.03 r0 top
R71 "R0402" R0402 1318.9,-866.14 r270 top
R72 "R0402" R0402 1358.27,-866.14 r90 top
R73 "R0402" R0402 1251.97,-1248.03 r180 top
R74 "R0402" R0402 1129.92,-968.5 r180 top
R75 "R0402" R0402 1409.45,-1248.03 r0 top
R76 "R0402" R0402 1330.71,-1248.03 r180 top
R77 "R0402" R0402 -1311.02,-1137.8 r180 top
R78 "R0402" R0402 -1311.02,-1169.29 r180 top
R79 "R0402" R0402 -1311.02,-1106.3 r180 top
R80 "R0402" R0402 -1311.02,-1074.8 r180 top
R81 "R0402" R0402 -1342.52,-791.34 r0 top
R82 "R0402" R0402 1692.91,1078.74 r180 top
R83 "R0402" R0402 1614.17,1122.05 r180 top
R84 "R0402" R0402 1614.17,1078.74 r180 top
R85 "R0402" R0402 1181.1,1476.38 r180 top
R86 "R0402" R0402 1614.17,1236.22 r0 top
R87 "R0402" R0402 2082.68,-877.95 r0 top
R88 "R0402" R0402 1874.02,-850.39 r90 top
R89 "R0402" R0402 2082.68,-799.21 r0 top
R90 "R0402" R0402 2169.29,-1031.5 r180 top
R91 "R0402" R0402 2169.29,-996.06 r180 top
R92 "R0402" R0402 2082.68,-838.58 r0 top
R100 "R0402" R0402 -2385.83,665.35 r180 top
R101 "R0402" R0402 -3019.68,1366.14 r0 top
R116 "R0402" R0402 -2074.8,397.64 r0 top
R117 "R0402" R0402 -2074.8,468.5 r180 top
R118 "R0402" R0402 -2385.83,468.5 r180 top
R119 "R0805" R0805 -1633.86,-1145.67 r180 top
R120 "R0402" R0402 -1279.53,535.43 r90 top
R156 "R0603" R0603 -2452.76,-1157.48 r180 top
R157 "R0402" R0402 -2192.91,-1192.91 r180 top
R158 "R0402" R0402 -2192.91,-1153.54 r0 top
R159 "R0402" R0402 -2330.71,-1374.02 r270 top
R228 "R0402" R0402 -1228.35,535.43 r90 top
R229 "R0402" R0402 -1377.95,535.43 r90 top
R230 "R0402" R0402 -1330.71,535.43 r90 top
R231 "R0402" R0402 -1476.38,535.43 r90 top
R232 "R0402" R0402 -1429.13,535.43 r90 top
R233 "R0402" R0402 -2385.83,106.3 r0 top
R234 "R0402" R0402 -1216.54,1307.09 r180 top
R235 "R0402" R0402 -1141.73,1307.09 r0 top
R236 "R0402" R0402 -1232.28,1362.2 r270 top
R237 "R0402" R0402 -1125.98,1362.2 r270 top
R238 "R0402" R0402 -2192.91,-1232.28 r0 top
R239 "R0402" R0402 -2192.91,-1271.65 r180 top
R240 "R0402" R0402 -2192.91,-1114.17 r180 top
R241 "R0402" R0402 -2043.31,-1181.1 r90 top
R242 "R0402" R0402 -1370.08,1291.34 r270 top
R243 "R0402" R0402 -1401.57,1291.34 r270 top
R333 "R0402" R0402 -1141.73,1275.59 r0 top
R334 "R0402" R0402 -1216.54,1275.59 r180 top
RA1 "R0402" R0402 -200.79,1964.57 r270 top
RA2 "C0402" C0402 -614.17,1720.47 r0 top
RA3 "R0402" R0402 -220.47,2019.68 r180 top
RA4 "R0402" R0402 -496.06,1826.77 r90 top
RA5 "R0402" R0402 -279.53,2078.74 r270 top
RA6 "R0402" R0402 -314.96,2078.74 r270 top
RA7 "R0402" R0402 -614.17,1562.99 r0 top
RA8 "R0402" R0402 -614.17,1598.43 r180 top
RA9 "R0402" R0402 -110.24,1437.01 r0 top
RA10 "R0402" R0402 -374.02,1984.25 r0 top
RA11 "R0402" R0402 -192.91,1594.49 r0 top
RA12 "R0402" R0402 -374.02,1944.88 r0 top
RA13 "R0402" R0402 -192.91,1437.01 r0 top
RA14 "R0402" R0402 -562.99,1429.13 r90 top
RA15 "R0402" R0402 -574.8,1826.77 r270 top
RA16 "R0402" R0402 -614.17,1826.77 r90 top
RA17 "R0402" R0402 -192.91,1476.38 r180 top
RA18 "R0402" R0402 -192.91,1712.6 r180 top
RA19 "R0402" R0402 -110.24,1476.38 r0 top
RA20 "R0402" R0402 -192.91,1751.97 r0 top
RA21 "R0402" R0402 -480.31,1984.25 r0 top
RA22 "R0402" R0402 -255.91,1429.13 r270 top
RA23 "R0402" R0402 -307.09,1429.13 r270 top
RA24 "R0402" R0402 -440.94,1429.13 r90 top
RA25 "R0402" R0402 -480.31,1944.88 r0 top
RA26 "R0402" R0402 -456.69,1826.77 r90 top
RA27 "R0402" R0402 -653.54,2003.94 r90 top
RA28 "R0402" R0402 -744.09,1980.31 r0 top
RA29 "R0402" R0402 -744.09,1944.88 r0 top
RA30 "R0402" R0402 -653.54,1929.13 r90 top
RA31 "R0402" R0402 -1799.21,1799.21 r90 top
RA32 "R0402" R0402 -1755.91,1799.21 r90 top
RE1 "R0402" R0402 1614.17,1035.43 r180 top
RE2 "R0402" R0402 1181.1,1228.35 r0 top
RE3 "R0402" R0402 1181.1,1129.92 r0 top
RE4 "R0402" R0402 1614.17,1322.83 r180 top
RE5 "R0402" R0402 1244.09,940.94 r270 top
RE6 "R0402" R0402 1181.1,1055.12 r0 top
RE7 "R0402" R0402 1181.1,1011.81 r0 top
RE8 "R0402" R0402 1287.4,940.94 r270 top
RE9 "R0402" R0402 1330.71,940.94 r270 top
RE10 "R0402" R0402 1460.63,940.94 r90 top
RE11 "R0402" R0402 1417.32,940.94 r90 top
RE12 "R0402" R0402 1614.17,1165.35 r180 top
RE13 "R0402" R0402 1200.79,940.94 r270 top
RE14 "R0402" R0402 1503.94,940.94 r90 top
RE15 "R0402" R0402 1374.02,940.94 r90 top
RL1 "R0402" R0402 -2590.55,-145.67 r180 top
RL2 "R0402" R0402 -2590.55,-66.93 r180 top
RN1 "R0402" R0402 -1712.6,1799.21 r90 top
RN2 "R0402" R0402 -1838.58,1799.21 r90 top
RU1 "R0402" R0402 -1964.57,1385.83 r0 top
RU2 "R0402" R0402 -2047.24,1385.83 r180 top
TP1 "BJ_LOGO" BJ_LOGO 1374.02,-342.52 r90 top
TP2 "6X6" 6X6 409.45,1370.08 r0 top
U1 "HELPERA733D-2" HELPERA733D-2 0,0 r90 top
U2 "SOT23-6" SOT23-6 -2502.56,-874.4 r180 top
U3 "SOT23-6" SOT23-6 -2224.41,70.87 r90 top
U5 "SOT23" SOT23 -74.8,2086.61 r270 top
U6 "SOT23-5" SOT23-5 2177.17,1854.33 r90 top
U7 "SOT23-6" SOT23-6 2177.17,2161.42 r90 top
U8 "ESOP-8" ESOP-8 -976.07,1845.16 r0 top
U9 "SO8NB" SO8NB 1295.28,-1070.87 r180 top
U10 "QFN40" QFN40 1405.51,1165.35 r0 top
U11 "SSOP16_SL2.1S" SSOP16_SL2.1S 133.86,1783.46 r0 top
U12 "MSOP-10" MSOP-10 98.43,1606.3 r0 top
U13 "SOT23-5" SOT23-5 -2007.87,1472.44 r270 top
U14 "HDMIQ" HDMIQ 2342.52,-653.54 r90 top
U15 "DFN2510-10_L2.5-W1.0-P0.50-BL" DFN2510-10_L2.5-W1.0-P0.50-BL 2169.29,-641.73 r270 top
U16 "DFN2510-10_L2.5-W1.0-P0.50-BL" DFN2510-10_L2.5-W1.0-P0.50-BL 2169.29,-759.84 r270 top
U42 "SSOP16_SL2.1S" SSOP16_SL2.1S -2480.31,1437.01 r0 top
U43 "SOT23-6" SOT23-6 -2224.41,429.13 r90 top
U44 "SOT23-6" SOT23-6 -2322.83,-1212.6 r180 top
UA1 "QFN40" QFN40 -398.43,1621.09 r0 top
X1 "X3225" X3225 1763.78,1208.66 r270 top
X2 "X3225" X3225 318.9,1929.13 r270 top
X3 "X3225" X3225 -2259.84,1452.76 r180 top

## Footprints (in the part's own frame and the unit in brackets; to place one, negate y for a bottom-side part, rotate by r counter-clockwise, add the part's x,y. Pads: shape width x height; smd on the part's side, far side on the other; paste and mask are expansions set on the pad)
6X6 [mil]
  silkscreen extent 0,0 236,236
4018 [mm]
  rect 1.5x3.7 smd: 1(-1.5,0) 2(1.5,0)
  silkscreen extent -2.5,-2 2.5,2
BEEP_9042 [mm]
  oval 1.7x1.524 hole 0.8 slot 1.2 at 0 deg: 1(-2.5,0) 2(2.5,-0.13)
  silkscreen extent -4.5,-4.5 4.5,4.5
BJ_LOGO [mil]
  silkscreen extent -205,-203 191,187
C0402 [mm]
  rect 0.5x0.5 smd mask+0.05: 1(-0.425,0) 2(0.425,0)
  silkscreen extent -0.91,-0.43 0.91,0.43
C0603 [mm]
  rect 0.76x0.76 smd mask+0.05: 1(-0.71,0) 2(0.71,0)
  silkscreen extent -1.37,-0.71 1.37,0.71
C0805 [mil]
  rect 37x50 smd: 1(-40,0) 2(40,0)
  silkscreen extent -66,-32 66,32
D0603 [mil]
  rect 30x32 smd: 1(-30,0) 2(30,0)
  silkscreen extent -55,-25 55,25
D0805 [mil]
  rect 37x50 smd: 1(-40,0) 2(40,0)
  silkscreen extent -73,-36 75,36
DC470 [mm]
  oval 1.2x4 hole 0.6 slot 3.5 at 90 deg: 1(6.2,0)
  oval 1.2x3 hole 0.6 slot 2.5 at 90 deg: 2(0,0)
  oval 3x1.2 hole 0.6 slot 2.5 at 0 deg: 3(3.2,-4.7)
  silkscreen extent -7.7,-4.52 6.18,4.5
DFN2510-10_L2.5-W1.0-P0.50-BL [mm]
  rect 0.2x0.665 smd paste+0 mask+0.051: 1(-1,-0.433) 2(-0.5,-0.433) 4(0.5,-0.433) 5(1,-0.433) 6(1,0.433) 7(0.5,0.433) 9(-0.5,0.433) 10(-1,0.433)
  rect 0.4x0.665 smd paste+0.001 mask+0.051: 3(0,-0.433) 8(0,0.433)
  silkscreen extent -1.33,-1.11 1.33,0.58
DVA [mm]
  round 3.3 hole 3.3 unplated: 1(0,0)
DVE [mm]
  round 3.6 hole 3.2: 1(0,0)
ESD0402 [mil]
  rect 24x20 smd: 1(-18,0) 2(18,0)
  silkscreen extent -36,-17 36,17
ESOP-8 [mil]
  oval 24x74 smd: 1(-75,-113) 2(-25,-113) 3(25,-113) 4(75,-113) 5(75,113) 6(25,113) 7(-25,113) 8(-75,113)
  rect 124x89 smd: 9(0,0)
  silkscreen extent -95,-65 95,65
FH35C-39S-0.3SHW [mm]
  rect 0.3x1.2 smd: 1(-5.7,-1.5) 2(-5.4,1.7) 3(-5.1,-1.5) 4(-4.8,1.7) 5(-4.5,-1.5) 6(-4.2,1.7) 7(-3.9,-1.5) 8(-3.6,1.7) 9(-3.3,-1.5) 10(-3,1.7) 11(-2.7,-1.5) 12(-2.4,1.7) 13(-2.1,-1.5) 14(-1.8,1.7) 15(-1.5,-1.5) 16(-1.2,1.7) 17(-0.9,-1.5) 18(-0.6,1.7) 19(-0.3,-1.5) 20(0,1.7) 21(0.3,-1.5) 22(0.6,1.7) 23(0.9,-1.5) 24(1.2,1.7) 25(1.5,-1.5) 26(1.8,1.7) 27(2.1,-1.5) 28(2.4,1.7) 29(2.7,-1.5) 30(3,1.7) 31(3.3,-1.5) 32(3.6,1.7) 33(3.9,-1.5) 34(4.2,1.7) 35(4.5,-1.5) 36(4.8,1.7) 37(5.1,-1.5) 38(5.4,1.7) 39(5.7,-1.5)
  rect 0.3x1.15 smd: 40(6.35,-1.062) 41(-6.35,-1.062)
  silkscreen extent -6.7,-2.94 6.7,2.43
FPC30-0.5-1 [mm]
  rect 1.15x0.25 smd: 1(-1.75,7.25) 2(-1.75,6.75) 3(-1.75,6.25) 4(-1.75,5.75) 5(-1.75,5.25) 6(-1.75,4.75) 7(-1.75,4.25) 8(-1.75,3.75) 9(-1.75,3.25) 10(-1.75,2.75) 11(-1.75,2.25) 12(-1.75,1.75) 13(-1.75,1.25) 14(-1.75,0.75) 15(-1.75,0.25) 16(-1.75,-0.25) 17(-1.75,-0.75) 18(-1.75,-1.25) 19(-1.75,-1.75) 20(-1.75,-2.25) 21(-1.75,-2.75) 22(-1.75,-3.25) 23(-1.75,-3.75) 24(-1.75,-4.25) 25(-1.75,-4.75) 26(-1.75,-5.25) 27(-1.75,-5.75) 28(-1.75,-6.25) 29(-1.75,-6.75) 30(-1.75,-7.25)
  rect 2.7x2.4 smd: 31(0.5,-9.25) 32(0.5,9.5)
  silkscreen extent -2.98,-10.13 3.94,10.48
FPC40-0.5MM-UP [mm]
  rect 0.3x1.5 smd: 1(19.5,-0.5) 2(19,-0.5) 3(18.5,-0.5) 4(18,-0.5) 5(17.5,-0.5) 6(17,-0.5) 7(16.5,-0.5) 8(16,-0.5) 9(15.5,-0.5) 10(15,-0.5) 11(14.5,-0.5) 12(14,-0.5) 13(13.5,-0.5) 14(13,-0.5) 15(12.5,-0.5) 16(12,-0.5) 17(11.5,-0.5) 18(11,-0.5) 19(10.5,-0.5) 20(10,-0.5) 21(9.5,-0.5) 22(9,-0.5) 23(8.5,-0.5) 24(8,-0.5) 25(7.5,-0.5) 26(7,-0.5) 27(6.5,-0.5) 28(6,-0.5) 29(5.5,-0.5) 30(5,-0.5) 31(4.5,-0.5) 32(4,-0.5) 33(3.5,-0.5) 34(3,-0.5) 35(2.5,-0.5) 36(2,-0.5) 37(1.5,-0.5) 38(1,-0.5) 39(0.5,-0.5) 40(0,-0.5)
  rect 1.8x3.8 smd: 41(-1.796,-3.345) 42(21.191,-3.35)
  silkscreen extent -2.71,-5.28 22.1,-0.63
FPC_0.5_6P_DOWN [mm]
  rect 0.3x1.25 smd: 1(0,0) 2(0.5,0) 3(1,0) 4(1.5,0) 5(2,0) 6(2.5,0)
  rrect0% 3x3 smd: 7(-2,2.3) 8(4.5,2.3)
  silkscreen extent -3.44,-0.93 5.93,4.9
HDMIQ [mm]
  rect 0.28x2.6 smd: 1(4.5,0) 2(4,0) 3(3.5,0) 4(3,0) 5(2.5,0) 6(2,0) 7(1.5,0) 8(1,0) 9(0.5,0) 10(0,0) 11(-0.5,0) 12(-1,0) 13(-1.5,0) 14(-2,0) 15(-2.5,0) 16(-3,0) 17(-3.5,0) 18(-4,0) 19(-4.5,0)
  oval 1.5x3.3 hole 1.016 slot 2.286 at 90 deg: 20(-7.25,-0.76) 21(7.25,-0.76)
  oval 1.5x2.616 hole 1.016 slot 1.778 at 90 deg: 22(-7.25,-6.72) 23(7.26,-6.732)
  silkscreen extent -8.3,-11.41 8.3,1.39
HDR2X20$2F$2.0 [mil]
  rect 60x60 hole 32: 1(0,0)
  round 60 hole 32: 2(0,78.74) 3(78.74,0) 4(78.74,78.74) 5(157.48,0) 6(157.48,78.74) 7(236.22,0) 8(236.22,78.74) 9(314.96,0) 10(314.96,78.74) 11(393.7,0) 12(393.7,78.74) 13(472.44,0) 14(472.44,78.74) 15(551.18,0) 16(551.18,78.74) 17(629.92,0) 18(629.92,78.74) 19(708.66,0) 20(708.66,78.74) 21(787.4,0) 22(787.4,78.74) 23(866.14,0) 24(866.14,78.74) 25(944.88,0) 26(944.88,78.74) 27(1023.62,0) 28(1023.62,78.74) 29(1102.36,0) 30(1102.36,78.74) 31(1181.1,0) 32(1181.1,78.74) 33(1259.84,0) 34(1259.84,78.74) 35(1338.58,0) 36(1338.58,78.74) 37(1417.32,0) 38(1417.32,78.74) 39(1496.06,0) 40(1496.06,78.74)
  silkscreen extent -188,-95 1684,148
HELPERA733D-2 [mm]
  oval 1x0.6 smd: 1(-30,18) 2(-30,17) 3(-30,16) 4(-30,15) 5(-30,14) 6(-30,13) 7(-30,12) 8(-30,11) 9(-30,10) 10(-30,9) 11(-30,8) 12(-30,7) 13(-30,6) 14(-30,5) 15(-30,4) 16(-30,3) 17(-30,2) 18(-30,1) 19(-30,0) 20(-30,-1) 21(-30,-2) 22(-30,-3) 23(-30,-4) 24(-30,-5) 25(-30,-6) 26(-30,-7) 27(-30,-8) 28(-30,-9) 29(-30,-10) 30(-30,-11) 31(-30,-12) 32(-30,-13) 33(-30,-14) 34(-30,-15) 35(-30,-16) 36(-30,-17) 37(-30,-18) 95(30,-18) 96(30,-17) 97(30,-16) 98(30,-15) 99(30,-14) 100(30,-13) 101(30,-12) 102(30,-11) 103(30,-10) 104(30,-9) 105(30,-8) 106(30,-7) 107(30,-6) 108(30,-5) 109(30,-4) 110(30,-3) 111(30,-2) 112(30,-1) 113(30,0) 114(30,1) 115(30,2) 116(30,3) 117(30,4) 118(30,5) 119(30,6) 120(30,7) 121(30,8) 122(30,9) 123(30,10) 124(30,11) 125(30,12) 126(30,13) 127(30,14) 128(30,15) 129(30,16) 130(30,17) 131(30,18)
  oval 0.6x1 smd: 38(-28,-20) 39(-27,-20) 40(-26,-20) 41(-25,-20) 42(-24,-20) 43(-23,-20) 44(-22,-20) 45(-21,-20) 46(-20,-20) 47(-19,-20) 48(-18,-20) 49(-17,-20) 50(-16,-20) 51(-15,-20) 52(-14,-20) 53(-13,-20) 54(-12,-20) 55(-11,-20) 56(-10,-20) 57(-9,-20) 58(-8,-20) 59(-7,-20) 60(-6,-20) 61(-5,-20) 62(-4,-20) 63(-3,-20) 64(-2,-20) 65(-1,-20) 66(0,-20) 67(1,-20) 68(2,-20) 69(3,-20) 70(4,-20) 71(5,-20) 72(6,-20) 73(7,-20) 74(8,-20) 75(9,-20) 76(10,-20) 77(11,-20) 78(12,-20) 79(13,-20) 80(14,-20) 81(15,-20) 82(16,-20) 83(17,-20) 84(18,-20) 85(19,-20) 86(20,-20) 87(21,-20) 88(22,-20) 89(23,-20) 90(24,-20) 91(25,-20) 92(26,-20) 93(27,-20) 94(28,-20) 132(28,20) 133(27,20) 134(26,20) 135(25,20) 136(24,20) 137(23,20) 138(22,20) 139(21,20) 140(20,20) 141(19,20) 142(18,20) 143(17,20) 144(16,20) 145(15,20) 146(14,20) 147(13,20) 148(12,20) 149(11,20) 150(10,20) 151(9,20) 152(8,20) 153(7,20) 154(6,20) 155(5,20) 156(4,20) 157(3,20) 158(2,20) 159(1,20) 160(0,20) 161(-1,20) 162(-2,20) 163(-3,20) 164(-4,20) 165(-5,20) 166(-6,20) 167(-7,20) 168(-8,20) 169(-9,20) 170(-10,20) 171(-11,20) 172(-12,20) 173(-13,20) 174(-14,20) 175(-15,20) 176(-16,20) 177(-17,20) 178(-18,20) 179(-19,20) 180(-20,20) 181(-21,20) 182(-22,20) 183(-23,20) 184(-24,20) 185(-25,20) 186(-26,20) 187(-27,20) 188(-28,20)
  round 2 smd: 189(-3,-7.3) 190(-6,-8.2)
  silkscreen extent -31.1,-21.1 31.1,21.1
HY911130A [mil]
  round 60 hole 35: 1(0,0) 2(-50.39,100) 3(-100,0) 4(-150.39,100) 5(-200,0) 6(-250.39,100) 7(-300,0) 8(-350.39,100) 9(-400,0) 10(-450.39,100) 13(-377.56,542.91) 14(-477.56,542.91)
  round 60 hole 40.16: 11(44.09,542.91) 12(-55.91,542.91)
  round 88.58 / inner round 78.74 / far side round 78.74 hole 64.17: 15(79.92,229.92) 16(-529.92,229.92)
  round 127.95 hole 127.95: 17(0,350) 18(-450,350)
  silkscreen extent -542,-76 92,780
KEY_3X4 [mm]
  rect 2x1.35 smd: 1(-2,0) 2(2,0)
  silkscreen extent -2,-1.5 2,1.5
L0603 [mm]
  rect 1x0.8 smd: 1(0.025,0.025) 2(1.525,0.025)
  silkscreen extent -0.62,-0.72 2.18,0.78
M.2-M-KEY [mm]
  rect 0.3x1.55 smd mask+0.05: 1(-9.25,3.75) 2(-9,-3.8) 3(-8.75,3.75) 4(-8.5,-3.8) 5(-8.25,3.75) 6(-8,-3.8) 7(-7.75,3.75) 8(-7.5,-3.8) 9(-7.25,3.75) 10(-7,-3.8) 11(-6.75,3.75) 12(-6.5,-3.8) 13(-6.25,3.75) 14(-6,-3.8) 15(-5.75,3.75) 16(-5.5,-3.8) 17(-5.25,3.75) 18(-5,-3.8) 19(-4.75,3.75) 20(-4.5,-3.8) 21(-4.25,3.75) 22(-4,-3.8) 23(-3.75,3.75) 24(-3.5,-3.8) 25(-3.25,3.75) 26(-3,-3.8) 27(-2.75,3.75) 28(-2.5,-3.8) 29(-2.25,3.75) 30(-2,-3.8) 31(-1.75,3.75) 32(-1.5,-3.8) 33(-1.25,3.75) 34(-1,-3.8) 35(-0.75,3.75) 36(-0.5,-3.8) 37(-0.25,3.75) 38(0,-3.8) 39(0.25,3.75) 40(0.5,-3.8) 41(0.75,3.75) 42(1,-3.8) 43(1.25,3.75) 44(1.5,-3.8) 45(1.75,3.75) 46(2,-3.8) 47(2.25,3.75) 48(2.5,-3.8) 49(2.75,3.75) 50(3,-3.8) 51(3.25,3.75) 52(3.5,-3.8) 53(3.75,3.75) 54(4,-3.8) 55(4.25,3.75) 56(4.5,-3.8) 57(4.75,3.75) 58(5,-3.8) 67(7.25,3.75) 68(7.5,-3.8) 69(7.75,3.75) 70(8,-3.8) 71(8.25,3.75) 72(8.5,-3.8) 73(8.75,3.75) 74(9,-3.8) 75(9.25,3.75)
  rect 1.2x2.75 smd paste+0.1 mask+0.05: 76(-10.35,2.975) 77(10.35,2.975)
  round 4 / inner round 4 / far side round 2.2 hole 2.2: 78(0,-29.8) 79(0,-41.8)
  round 1.6 hole 1.6 unplated mask+0.05: MH1(10,-1.525)
  round 1.1 hole 1.1 unplated: MH2(-10,-1.525)
  Top keep-out region: -9.2,-1.525 -9.261,-1.219 -9.434,-0.959 -9.694,-0.786 -10,-0.725 -10,-0.725 -10.306,-0.786 -10.566,-0.959 -10.739,-1.219 -10.8,-1.525 -10.8,-1.525 -10.739,-1.831 -10.566,-2.091 -10.306,-2.264 -10,-2.325 -10,-2.325 -9.694,-2.264 -9.434,-2.091 -9.261,-1.831 -9.2,-1.525
  Top keep-out region: 11.05,-1.525 10.97,-1.123 10.742,-0.783 10.402,-0.555 10,-0.475 10,-0.475 9.598,-0.555 9.258,-0.783 9.03,-1.123 8.95,-1.525 8.95,-1.525 9.03,-1.927 9.258,-2.268 9.598,-2.495 10,-2.575 10,-2.575 10.402,-2.495 10.742,-2.268 10.97,-1.927 11.05,-1.525
  silkscreen extent -12,-41.78 12,5.52
MARK [mil]
  round 40 all layers, no hole: 1(0,0)
MIC6050 [mm]
  round 1.2 hole 0.6: 1(1,-1) 2(1,1)
  silkscreen extent -3.1,-3.1 3.1,3.1
MINI_PCIEX1-52P-5.2H [mm]
  rect 0.61x2.007 smd: 1(-11.8,-30.775) 2(-11.4,-21.575) 3(-11,-30.775) 4(-10.6,-21.575) 5(-10.2,-30.775) 6(-9.8,-21.575) 7(-9.4,-30.775) 8(-9,-21.575) 9(-8.6,-30.775) 10(-8.2,-21.575) 11(-7.8,-30.775) 12(-7.4,-21.575) 13(-7,-30.775) 14(-6.6,-21.575) 15(-6.2,-30.775) 16(-5.8,-21.575) 17(-2.2,-30.775) 18(-1.8,-21.575) 19(-1.4,-30.775) 20(-1,-21.575) 21(-0.6,-30.775) 22(-0.2,-21.575) 23(0.2,-30.775) 24(0.6,-21.575) 25(1,-30.775) 26(1.4,-21.575) 27(1.8,-30.775) 28(2.2,-21.575) 29(2.6,-30.775) 30(3,-21.575) 31(3.4,-30.775) 32(3.8,-21.575) 33(4.2,-30.775) 34(4.6,-21.575) 35(5,-30.775) 36(5.4,-21.575) 37(5.8,-30.775) 38(6.2,-21.575) 39(6.6,-30.775) 40(7,-21.575) 41(7.4,-30.775) 42(7.8,-21.575) 43(8.2,-30.775) 44(8.6,-21.575) 45(9,-30.775) 46(9.4,-21.575) 47(9.8,-30.775) 48(10.2,-21.575) 49(10.6,-30.775) 50(11,-21.575) 51(11.4,-30.775) 52(11.8,-21.575)
  rect 4x4 / inner round 4 / far side rect 4x4 hole 2.3: _/2(-12.1,21.875) _/3(12.1,21.875)
  round 1.6 hole 1.6: G1(-12.5,-26.175)
  round 1.092 hole 1.092: G2(12.5,-26.175)
  rect 2.311x3.2 smd: M1(-14.65,-30.175) M2(14.65,-30.175)
  silkscreen extent -15,-30.27 15,24.78
MSOP-10 [mm]
  oval 1.2x0.25 smd paste-0.1 mask-0.1: 1(-2.55,1) 2(-2.55,0.5) 3(-2.55,0) 4(-2.55,-0.5) 5(-2.55,-1) 6(2.55,-1) 7(2.55,-0.5) 8(2.55,0) 9(2.55,0.5) 10(2.55,1)
  silkscreen extent -3.2,-1.8 3.2,1.8
MX1.25-2P [mil]
  oval 30x60 hole 19.68: 1(-24.61,0) 2(24.61,0)
  silkscreen extent -85,-85 85,47
NANO-SIM-7P [mm]
  rect 0.8x1.23 smd: 1(0.23,6.9) 2(-2.31,6.9) 3(-4.85,6.9) 5(1.5,6.9) 6(-1.04,6.9) 7(-3.58,6.9)
  rect 0.65x1.23 smd: 4(2.45,6.9)
  rect 0.7x2 smd: 8(-6.52,5.3) 9(6.48,5.3) 10(-6.52,-6.7) 11(6.48,-6.7)
  round 0.75 hole 0.75 unplated: 12(-5.02,-5.449) 13(3.48,-5.449)
  silkscreen extent -7.1,-9.3 7,7.7
PH-2.0-2P [mil]
  round 60 hole 35: 1(0,0) 2(78.74,0)
  silkscreen extent -79,-67 157,114
PH-2.0-4P [mil]
  round 60 hole 35: 1(0,0) 2(78.74,0) 3(157.48,0) 4(236.22,0)
  silkscreen extent -79,-67 315,114
PHD2.0-2X10 [mm]
  rect 1.2x1.2 / inner round 1.2 / far side rect 1.2x1.2 hole 0.8: 1(9,1)
  round 1.2 hole 0.8: 2(9,-1) 3(7,1) 4(7,-1) 5(5,1) 6(5,-1) 7(3,1) 8(3,-1) 9(1,1) 10(1,-1) 11(-1,1) 12(-1,-1) 13(-3,1) 14(-3,-1) 15(-5,1) 16(-5,-1) 17(-7,1) 18(-7,-1) 19(-9,1) 20(-9,-1)
  silkscreen extent -11,-2.5 11,2.5
PJ327F [mm]
  rect 2x3 smd paste+0.3: 1(2.1,-0.5) 2(7.4,-0.5) 3(9.8,6.5) 4(5.51,6.5) 5(2.11,6.5)
  round 1.5 hole 1.5 unplated: 6(9,3) 7(3,3)
  silkscreen extent -1.91,-0.2 12,6.2
QFN40 [mm]
  rect 0.2x0.8 smd paste+0.05: 1(1.8,2.55) 2(1.4,2.55) 3(1,2.55) 4(0.6,2.55) 5(0.2,2.55) 6(-0.2,2.55) 7(-0.6,2.55) 8(-1,2.55) 9(-1.4,2.55) 10(-1.8,2.55) 21(-1.8,-2.55) 22(-1.4,-2.55) 23(-1,-2.55) 24(-0.6,-2.55) 25(-0.2,-2.55) 26(0.2,-2.55) 27(0.6,-2.55) 28(1,-2.55) 29(1.4,-2.55) 30(1.8,-2.55)
  rect 0.8x0.2 smd paste+0.05: 11(-2.55,1.8) 12(-2.55,1.4) 13(-2.55,1) 14(-2.55,0.6) 15(-2.55,0.2) 16(-2.55,-0.2) 17(-2.55,-0.6) 18(-2.55,-1) 19(-2.55,-1.4) 20(-2.55,-1.8) 31(2.55,-1.8) 32(2.55,-1.4) 33(2.55,-1) 34(2.55,-0.6) 35(2.55,-0.2) 36(2.55,0.2) 37(2.55,0.6) 38(2.55,1) 39(2.55,1.4) 40(2.55,1.8)
  rrect0% 3x3 smd: 41(0,0)
  silkscreen extent -3.2,-3.2 3.2,3.2
R0402 [mm]
  rect 0.5x0.5 smd mask+0.05: 1(-0.425,0) 2(0.425,0)
  silkscreen extent -0.9,-0.4 0.9,0.4
R0603 [mm]
  rect 0.8x1 smd: 1(0,0.75) 2(0,-0.75)
  silkscreen extent -0.75,-1.4 0.75,1.4
R0805 [mil]
  rect 37x50 smd: 1(-40,0) 2(40,0)
  silkscreen extent -66,-32 66,32
RCLAMP0524P [mm]
  rect 0.2x0.675 smd: 1(1.05,0.435) 2(0.55,0.435) 4(-0.55,0.435) 5(-1.05,0.435) 6(-1.05,-0.44) 7(-0.55,-0.44) 9(0.55,-0.44) 10(1.05,-0.44)
  rect 0.4x0.675 smd: 3(-0.05,0.435) 8(-0.05,-0.44)
  silkscreen extent -1.22,-0.85 1.22,0.85
SML2520_1P2H$2F$4 [mil]
  rect 78.74x31.5 smd: 1(0,-39.35) 2(0,39.35)
  silkscreen extent -47,-59 47,59
SO8NB [mil]
  oval 24x74 smd: 1(-75,-113) 2(-25,-113) 3(25,-113) 4(75,-113) 5(75,113) 6(25,113) 7(-25,113) 8(-75,113)
  silkscreen extent -95,-65 95,65
SOD123 [mil]
  rrect0% 40x40 smd: 1(-69,0) 2(69,0)
  silkscreen extent -97,-39 97,39
SOD323 [mil]
  rect 37x50 smd: 1(-40,0) 2(40,0)
  silkscreen extent -73,-36 75,36
SOT23 [mil]
  rect 36x36 smd: 1(-37.5,-39) 2(37.5,-39)
  rect 36x50 smd: 3(0,41)
  silkscreen extent -55,-50 55,40
SOT23-5 [mm]
  rect 0.5x1.2 smd: 1(-0.95,-1.4) 2(0,-1.4) 3(0.95,-1.4) 4(0.95,1.4) 5(-0.95,1.4)
  silkscreen extent -1.45,-0.95 1.45,0.95
SOT23-6 [mm]
  rect 0.5x1.2 smd: 1(-0.95,-1.4) 2(0,-1.4) 3(0.95,-1.4) 4(0.95,1.4) 5(0,1.4) 6(-0.95,1.4)
  silkscreen extent -1.45,-0.95 1.45,0.95
SS-12F44(1P2T) [mm]
  oval 1.524x2 hole 0.6 slot 1 at 0 deg: 1(-3,0) 2(0,0) 3(3,0)
  oval 1.7x2.8 hole 0.7 slot 1.8 at 90 deg: 4(-6,0) 5(6,0)
  silkscreen extent -6,-3 6,3
SSOP16_SL2.1S [mm]
  oval 1x0.2 smd: 1(-1.9,1.855) 2(-1.9,1.325) 3(-1.9,0.795) 4(-1.9,0.265) 5(-1.9,-0.265) 6(-1.9,-0.795) 7(-1.9,-1.325) 8(-1.9,-1.855) 9(1.9,-1.855) 10(1.9,-1.325) 11(1.9,-0.795) 12(1.9,-0.265) 13(1.9,0.265) 14(1.9,0.795) 15(1.9,1.325) 16(1.9,1.855)
  silkscreen extent -1.2,-2.2 1.2,2.2
SW-1.27-6P [mm]
  rect 1.5x0.4 smd: 1(-3.9,1.27)
  rect 1.5x0.4 smd paste-0.05: 2(-3.9,0) 3(-3.9,-1.27) 4(3.95,-1.27) 5(3.95,0) 6(3.95,1.27)
  silkscreen extent -2.8,-1.91 2.85,1.91
TF_PUSH1 [mm]
  rect 0.7x1.6 smd: 1(-2.25,-7.25) 2(-1.15,-7.25) 3(-0.05,-7.25) 4(1.05,-7.25) 5(2.15,-7.25) 6(3.25,-7.25) 7(4.35,-7.25) 8(5.45,-7.25) 9(6.55,-7.25)
  rrect0% 1.5x1.5 smd: 10(-6.85,-6.75)
  rect 1.2x1.4 smd: 11(7.75,-6.75)
  rect 1.2x2.2 smd: 12(7.75,2.85) 13(-7.75,2.85)
  round 1 hole 1: _(4.95,3.25) _/2(-3.05,3.25)
  silkscreen extent -7.55,-7.53 7.55,10.1
USB-2A-03 [mil]
  round 60 hole 35: 1(0,0) 2(98.43,0) 3(177.17,0) 4(275.59,0) 5(0,-118.11) 6(98.43,-118.11) 7(177.17,-118.11) 8(275.59,-118.11)
  oval 80x150 hole 48 slot 100 at 90 deg: 9(-137.8,-216.54) 10(413.39,-216.54) 11(-137.8,0) 12(413.39,0)
  silkscreen extent -193,-640 469,89
USB_C [mm]
  oval 1x2.1 hole 0.6 slot 1.7 at 90 deg: 13(-1.12,-1.07) 14(7.52,-1.07)
  oval 1x1.8 / inner oval 1x1.6 / far side oval 1x1.6 hole 0.6 slot 1.4 at 90 deg: 15(-1.12,-5.25)
  oval 1x1.6 hole 0.6 slot 1.2 at 90 deg: 16(7.52,-5.25)
  round 0.65 hole 0.65 unplated: 17(0.31,-1.57) 18(6.09,-1.57)
  rect 0.6x1.64 smd: A1(0,0) A4(0.8,0) B1(6.4,0) B4(5.6,0)
  rect 0.3x1.64 smd: A5(1.95,0) A6(2.95,0) A7(3.45,0) A8(4.45,0) B5(4.95,0) B6(3.95,0) B7(2.45,0) B8(1.45,0)
  silkscreen extent -1.75,-7.65 8.15,-0.15
X3225 [mm]
  rect 1.4x1.2 smd: 1(-1.2,-0.85) 2(1.2,-0.85) 3(1.2,0.85) 4(-1.2,0.85)
  silkscreen extent -2.06,-1.58 2.08,1.58
XH-2.54-2P [mil]
  rect 60x60 / inner round 60 / far side rect 60x60 hole 37: 1(0,0)
  round 60 hole 37: 2(100,0)
  silkscreen extent -100,-98 200,138
XH-2.54-4P [mil]
  rect 60x60 hole 37: 1(150,0)
  round 60 hole 37: 2(50,0) 3(-50,0) 4(-150,0)
  silkscreen extent -245,-138 245,98

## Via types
v1: diameter 22, hole 12, Top to Bottom, 1469 vias
v2: diameter 39.37, hole 35.43, Top to Bottom, 2 vias

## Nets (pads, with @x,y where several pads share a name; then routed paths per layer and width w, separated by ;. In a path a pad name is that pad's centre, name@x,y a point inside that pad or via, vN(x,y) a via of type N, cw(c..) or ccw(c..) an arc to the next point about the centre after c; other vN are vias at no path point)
4G-EN: R118.1 U1.173 U43.4 | length 2811.4
  Top w6: R118.1@-2369.09,468.5 v1(-2334.65,468.5) -2293.11,468.5 -2291.14,466.54 U43.4@-2279.53,466.54 ; U1.173@-787.4,-511.81 -759.84,-511.81 -625.98,-377.95 -625.98,11.81 v1(-618.11,19.68)
  Bottom w6: v1(-2334.65,468.5) -2334.65,170.26 -2317.93,153.54 -1590.55,153.54 -1425.2,-11.81 -712.6,-11.81 -681.1,19.68 v1(-618.11,19.68)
